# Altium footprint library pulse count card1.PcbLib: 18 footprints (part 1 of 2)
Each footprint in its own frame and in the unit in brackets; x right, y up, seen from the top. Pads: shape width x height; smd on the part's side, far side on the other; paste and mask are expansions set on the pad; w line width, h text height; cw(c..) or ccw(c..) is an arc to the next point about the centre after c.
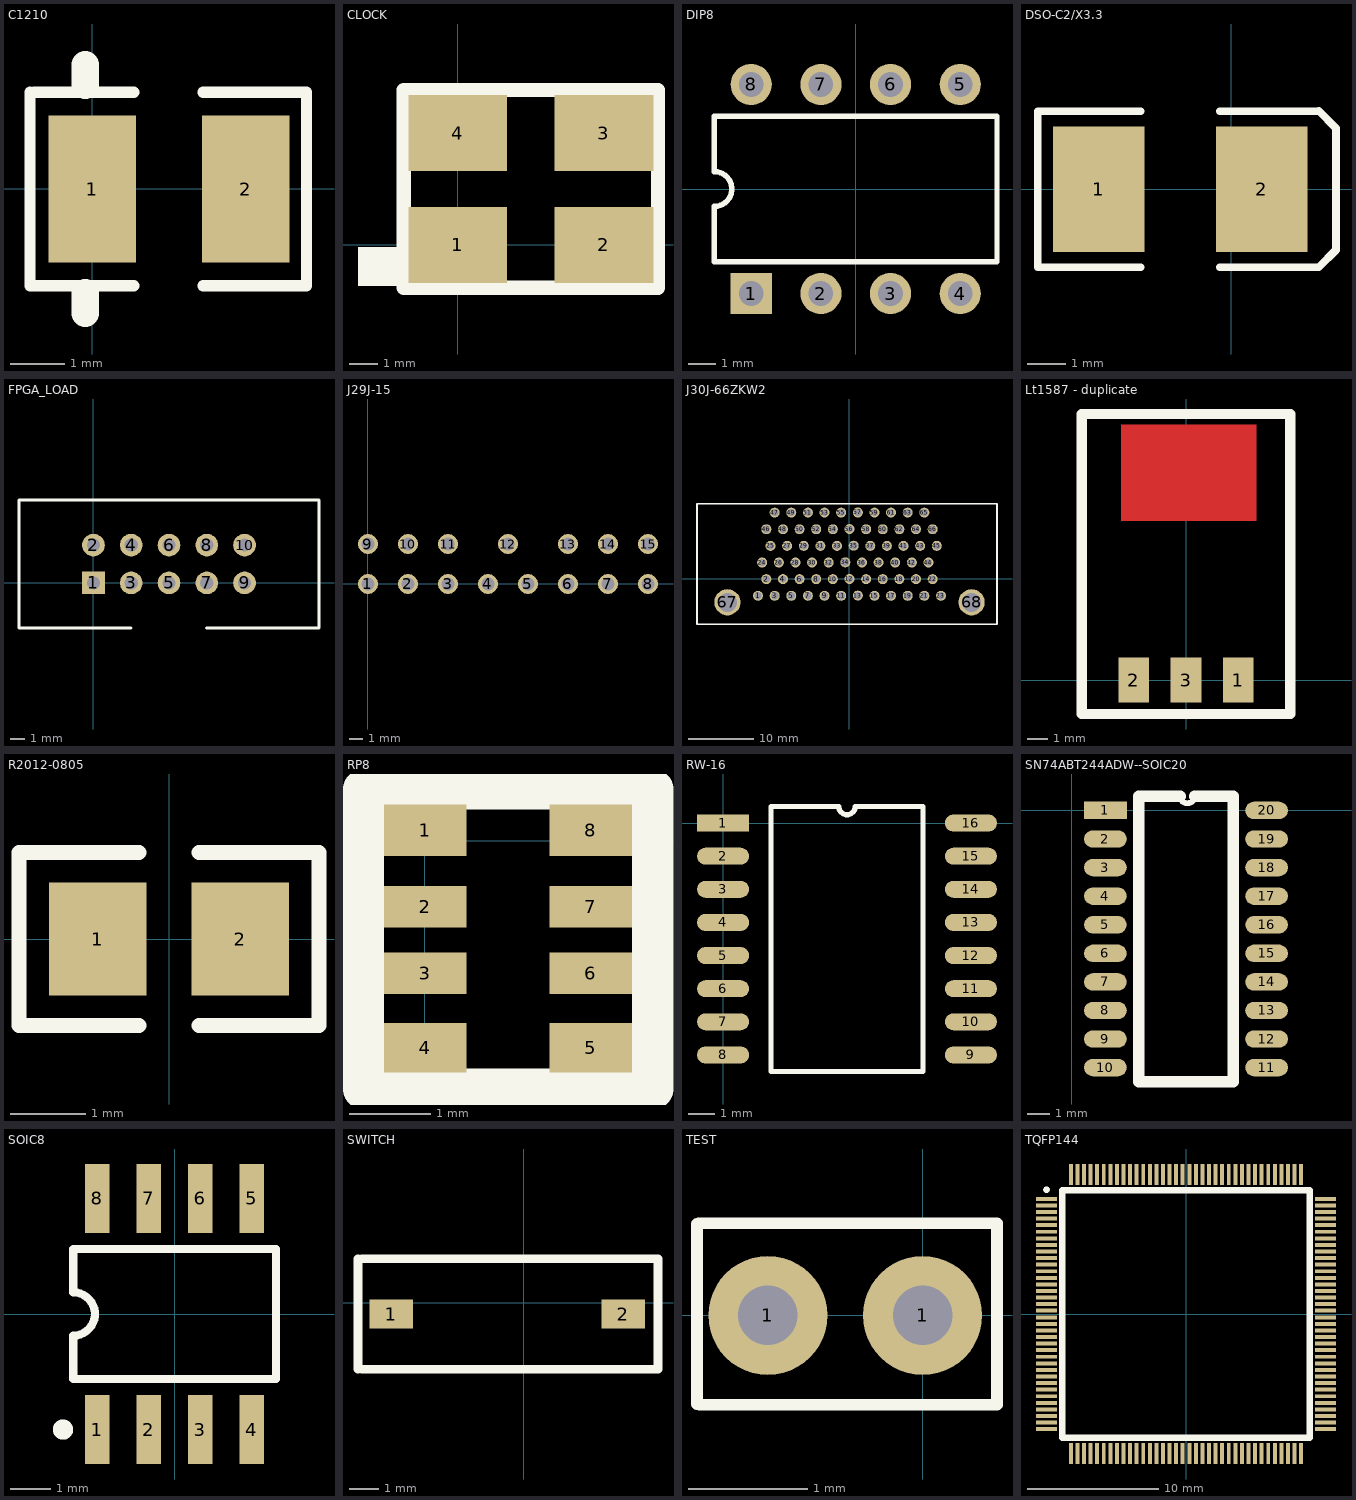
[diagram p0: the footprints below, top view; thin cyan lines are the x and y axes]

## C1210 [mil]
pads (2):
  rect 63x106 smd: 1(0,0) 2(111,0)
Top Overlay:
  lines w8: -45,70 -45,-70 30,-70 ; -42,70 30,70 ; 80,-70 155,-70 155,70 80,70
  lines w20: -5,-90 -5,-75 ; -5,75 -5,90

## CLOCK [mm]
pads (4):
  rect 3.5x2.7 smd: 1(0,0) 2(5.182,0) 3(5.182,3.962) 4(0,3.962)
Top Overlay:
  rectangle: -3.531,-1.448 -2.108,-0.076
  lines w0.508: -1.905,-0.514 -1.905,5.486 ; 7.095,-0.514 7.095,5.486 ; -1.905,5.486 7.095,5.486 ; -1.905,5.486 -1.905,-1.514 7.095,-1.514 7.095,5.486

## DIP8 [mm]
pads (8):
  rect 1.5x1.5 hole 0.9: 1(-3.81,-3.81)
  round 1.5 hole 0.9: 2(-1.27,-3.81) 3(1.27,-3.81) 4(3.81,-3.81) 5(3.81,3.81) 6(1.27,3.81) 7(-1.27,3.81) 8(-3.81,3.81)
Top Overlay:
  lines w0.2: -5.15,-2.65 5.15,-2.65 5.15,2.65 -5.15,2.65 -5.15,0.635 cw(c-5.15,0) -5.15,-0.635 -5.15,-2.65

## DSO-C2/X3.3 [mm]
pads (2):
  rect 2.4x3.3 smd: 1(-3.475,0.006) 2(0.808,0.006)
Top Overlay:
  lines w0.2: -2.375,-2.044 -5.075,-2.044 -5.075,2.056 -2.375,2.056 ; -0.292,-2.044 2.308,-2.044 2.758,-1.594 2.758,1.606 2.308,2.061 ; -0.292,2.056 2.308,2.056

## FPGA_LOAD [mil]
pads (10):
  rect 60x60 hole 35: 1(0,0)
  round 60 hole 35: 2(0,100) 3(100,0) 4(100,100) 5(200,0) 6(200,100) 7(300,0) 8(300,100) 9(400,0) 10(400,100)
Top Overlay:
  lines w8: 99,-119 -197,-119 -197,219 597,219 597,-119 299,-119

## J29J-15 [mm]
pads (15):
  round 1.5 hole 1: 1(0,0) 2(3,0) 3(6,0) 4(9,0) 5(12,0) 6(15,0) 7(18,0) 8(21,0) 9(0,3) 10(3,3) 11(6,3) 12(10.5,3) 13(15,3) 14(18,3) 15(21,3)

## J30J-66ZKW2 [mil]
pads (68):
  round 60 hole 43.31: 1(-550,-101) 2(-500,-1) 3(-450,-101) 4(-400,-1) 5(-350,-101) 6(-300,-1) 7(-250,-101) 8(-200,-1) 9(-150,-101) 10(-100,-1) 11(-50,-101) 12(0,0) 13(50,-100) 14(100,-1) 15(150,-101) 16(200,-1) 17(250,-101) 18(300,-1) 19(350,-101) 20(400,-1) 21(450,-101) 22(500,-1) 23(550,-101) 24(-525,99) 25(-475,199) 26(-425,99) 27(-375,199) 28(-325,99) 29(-275,199) 30(-225,99) 31(-175,199) 32(-125,99) 33(-75,199) 34(-25,100) 35(25,200) 36(75,99) 37(125,199) 38(175,99) 39(225,199) 40(275,99) 41(325,199) 42(375,99) 43(425,199) 44(475,99) 45(525,199) 46(-500,299) 47(-450,399) 48(-400,299) 49(-350,399) 50(-300,299) 51(-250,399) 52(-200,299) 53(-150,399) 54(-100,299) 55(-50,399) 56(0,300) 57(50,400) 58(100,299) 59(150,399) 60(200,299) 61(250,399) 62(300,299) 63(350,399) 64(400,299) 65(450,399) 66(500,299)
  round 157.48 hole 114.17: 67(-734.25,-140.37) 68(734.25,-140.37)
Top Overlay:
  lines w10: -917,-272 887,-272 887,452 -917,452 -917,-272

## Lt1587 - duplicate [mm]
pads (3):
  rect 1.5x2.2 smd: 1(2.54,0) 2(-2.54,0) 3(0,0)
Top Layer:
  rectangle: -3.175,7.747 3.429,12.446
Top Overlay:
  lines w0.508: -5.08,-1.651 5.08,-1.651 5.08,12.954 -5.08,12.954 -5.08,-1.651

## R2012-0805 [mm]
pads (2):
  rect 1.3x1.5 smd: 1(-0.95,0) 2(0.95,0)
Top Overlay:
  lines w0.2: -0.4,-1.15 -2,-1.15 -2,1.15 -0.4,1.15 ; 0.4,-1.15 2,-1.15 2,1.15 0.4,1.15

## RP8 [mil]
pads (8):
  rect 40x25 smd: 1(0.29,5) 8(80.29,5)
  rect 40x20 smd: 2(0.29,-32) 3(0.29,-64) 6(80.29,-64) 7(80.29,-32)
  rect 40x24 smd: 4(0.29,-100) 5(80.29,-100)
Top Overlay:
  lines w20: -29.71,-120 110.29,-120 110.29,25 -29.71,25 -29.71,-120

## RW-16 [mm]
pads (16):
  rect 2x0.65 smd: 1(0,0)
  oval 2x0.65 smd: 2(0,-1.27) 3(0,-2.54) 4(0,-3.81) 5(0,-5.08) 6(0,-6.35) 7(0,-7.62) 8(0,-8.89) 9(9.5,-8.89) 10(9.5,-7.62) 11(9.5,-6.35) 12(9.5,-5.08) 13(9.5,-3.81) 14(9.5,-2.54) 15(9.5,-1.27) 16(9.5,0)
Top Overlay:
  lines w0.2: 1.835,-9.525 1.835,0.635 4.432,0.635 ccw(c4.75,0.635) 5.067,0.635 7.665,0.635 7.665,-9.525 1.835,-9.525

## SN74ABT244ADW--SOIC20 [mm]
pads (20):
  rect 1.9x0.773 smd: 1(1.5,0)
  oval 1.9x0.773 smd: 2(1.5,-1.27) 3(1.5,-2.54) 4(1.5,-3.81) 5(1.5,-5.08) 6(1.5,-6.35) 7(1.5,-7.62) 8(1.5,-8.89) 9(1.5,-10.16) 10(1.5,-11.43) 11(8.66,-11.43) 12(8.66,-10.16) 13(8.66,-8.89) 14(8.66,-7.62) 15(8.66,-6.35) 16(8.66,-5.08) 17(8.66,-3.81) 18(8.66,-2.54) 19(8.66,-1.27) 20(8.66,0)
Top Overlay:
  lines w0.254: 4.822,0.635 ccw(c5.14,0.635) 5.457,0.635
  lines w0.508: 4.822,0.635 2.981,0.635 2.981,-12.065 7.172,-12.065 7.172,0.635 5.457,0.635

## SOIC8 [mm]
pads (8):
  rect 0.6x1.7 smd: 1(-1.905,-2.85) 2(-0.635,-2.85) 3(0.635,-2.85) 4(1.905,-2.85) 5(1.905,2.85) 6(0.635,2.85) 7(-0.635,2.85) 8(-1.905,2.85)
Top Overlay:
  circle w0.25: c-2.755,-2.85 r0.125
  lines w0.2: -2.5,-0.533 -2.5,-1.6 2.5,-1.6 2.5,1.6 -2.5,1.6 -2.5,0.533 ; -2.5,-0.533 ccw(c-2.5,0) -2.5,0.533

## SWITCH [mm]
pads (2):
  rect 1.5x1 smd: 1(-4.572,-0.381) 2(3.429,-0.381)
Top Overlay:
  lines w0.305: -5.715,-2.286 -5.715,1.524 ; -5.588,-2.286 4.619,-2.286 4.619,1.524 -5.588,1.524

## TEST [mm]
pads (2):
  round 1 hole 0.5: 1(-1.3,0) 1(0,0)
Top Overlay:
  lines w0.1: -1.895,-0.745 -1.895,0.77 ; -1.88,0.775 0.625,0.775 0.625,-0.74 ; -1.875,-0.75 0.625,-0.75

## TQFP144 [mm]
pads (144):
  rect 1.6x0.3 smd: 1(-10.6,8.75) 2(-10.6,8.25) 3(-10.6,7.75) 4(-10.6,7.25) 5(-10.6,6.75) 6(-10.6,6.25) 7(-10.6,5.75) 8(-10.6,5.25) 9(-10.6,4.75) 10(-10.6,4.25) 11(-10.6,3.75) 12(-10.6,3.25) 13(-10.6,2.75) 14(-10.6,2.25) 15(-10.6,1.75) 16(-10.6,1.25) 17(-10.6,0.75) 18(-10.6,0.25) 19(-10.6,-0.25) 20(-10.6,-0.75) 21(-10.6,-1.25) 22(-10.6,-1.75) 23(-10.6,-2.25) 24(-10.6,-2.75) 25(-10.6,-3.25) 26(-10.6,-3.75) 27(-10.6,-4.25) 28(-10.6,-4.75) 29(-10.6,-5.25) 30(-10.6,-5.75) 31(-10.6,-6.25) 32(-10.6,-6.75) 33(-10.6,-7.25) 34(-10.6,-7.75) 35(-10.6,-8.25) 36(-10.6,-8.75) 73(10.6,-8.75) 74(10.6,-8.25) 75(10.6,-7.75) 76(10.6,-7.25) 77(10.6,-6.75) 78(10.6,-6.25) 79(10.6,-5.75) 80(10.6,-5.25) 81(10.6,-4.75) 82(10.6,-4.25) 83(10.6,-3.75) 84(10.6,-3.25) 85(10.6,-2.75) 86(10.6,-2.25) 87(10.6,-1.75) 88(10.6,-1.25) 89(10.6,-0.75) 90(10.6,-0.25) 91(10.6,0.25) 92(10.6,0.75) 93(10.6,1.25) 94(10.6,1.75) 95(10.6,2.25) 96(10.6,2.75) 97(10.6,3.25) 98(10.6,3.75) 99(10.6,4.25) 100(10.6,4.75) 101(10.6,5.25) 102(10.6,5.75) 103(10.6,6.25) 104(10.6,6.75) 105(10.6,7.25) 106(10.6,7.75) 107(10.6,8.25) 108(10.6,8.75)
  rect 0.3x1.6 smd: 37(-8.75,-10.6) 38(-8.25,-10.6) 39(-7.75,-10.6) 40(-7.25,-10.6) 41(-6.75,-10.6) 42(-6.25,-10.6) 43(-5.75,-10.6) 44(-5.25,-10.6) 45(-4.75,-10.6) 46(-4.25,-10.6) 47(-3.75,-10.6) 48(-3.25,-10.6) 49(-2.75,-10.6) 50(-2.25,-10.6) 51(-1.75,-10.6) 52(-1.25,-10.6) 53(-0.75,-10.6) 54(-0.25,-10.6) 55(0.25,-10.6) 56(0.75,-10.6) 57(1.25,-10.6) 58(1.75,-10.6) 59(2.25,-10.6) 60(2.75,-10.6) 61(3.25,-10.6) 62(3.75,-10.6) 63(4.25,-10.6) 64(4.75,-10.6) 65(5.25,-10.6) 66(5.75,-10.6) 67(6.25,-10.6) 68(6.75,-10.6) 69(7.25,-10.6) 70(7.75,-10.6) 71(8.25,-10.6) 72(8.75,-10.6) 109(8.75,10.6) 110(8.25,10.6) 111(7.75,10.6) 112(7.25,10.6) 113(6.75,10.6) 114(6.25,10.6) 115(5.75,10.6) 116(5.25,10.6) 117(4.75,10.6) 118(4.25,10.6) 119(3.75,10.6) 120(3.25,10.6) 121(2.75,10.6) 122(2.25,10.6) 123(1.75,10.6) 124(1.25,10.6) 125(0.75,10.6) 126(0.25,10.6) 127(-0.25,10.6) 128(-0.75,10.6) 129(-1.25,10.6) 130(-1.75,10.6) 131(-2.25,10.6) 132(-2.75,10.6) 133(-3.25,10.6) 134(-3.75,10.6) 135(-4.25,10.6) 136(-4.75,10.6) 137(-5.25,10.6) 138(-5.75,10.6) 139(-6.25,10.6) 140(-6.75,10.6) 141(-7.25,10.6) 142(-7.75,10.6) 143(-8.25,10.6) 144(-8.75,10.6)
Top Overlay:
  circle w0.25: c-10.6,9.45 r0.125
  lines w0.508: -9.4,-9.4 9.4,-9.4 9.4,9.4 -9.4,9.4 -9.4,-9.4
